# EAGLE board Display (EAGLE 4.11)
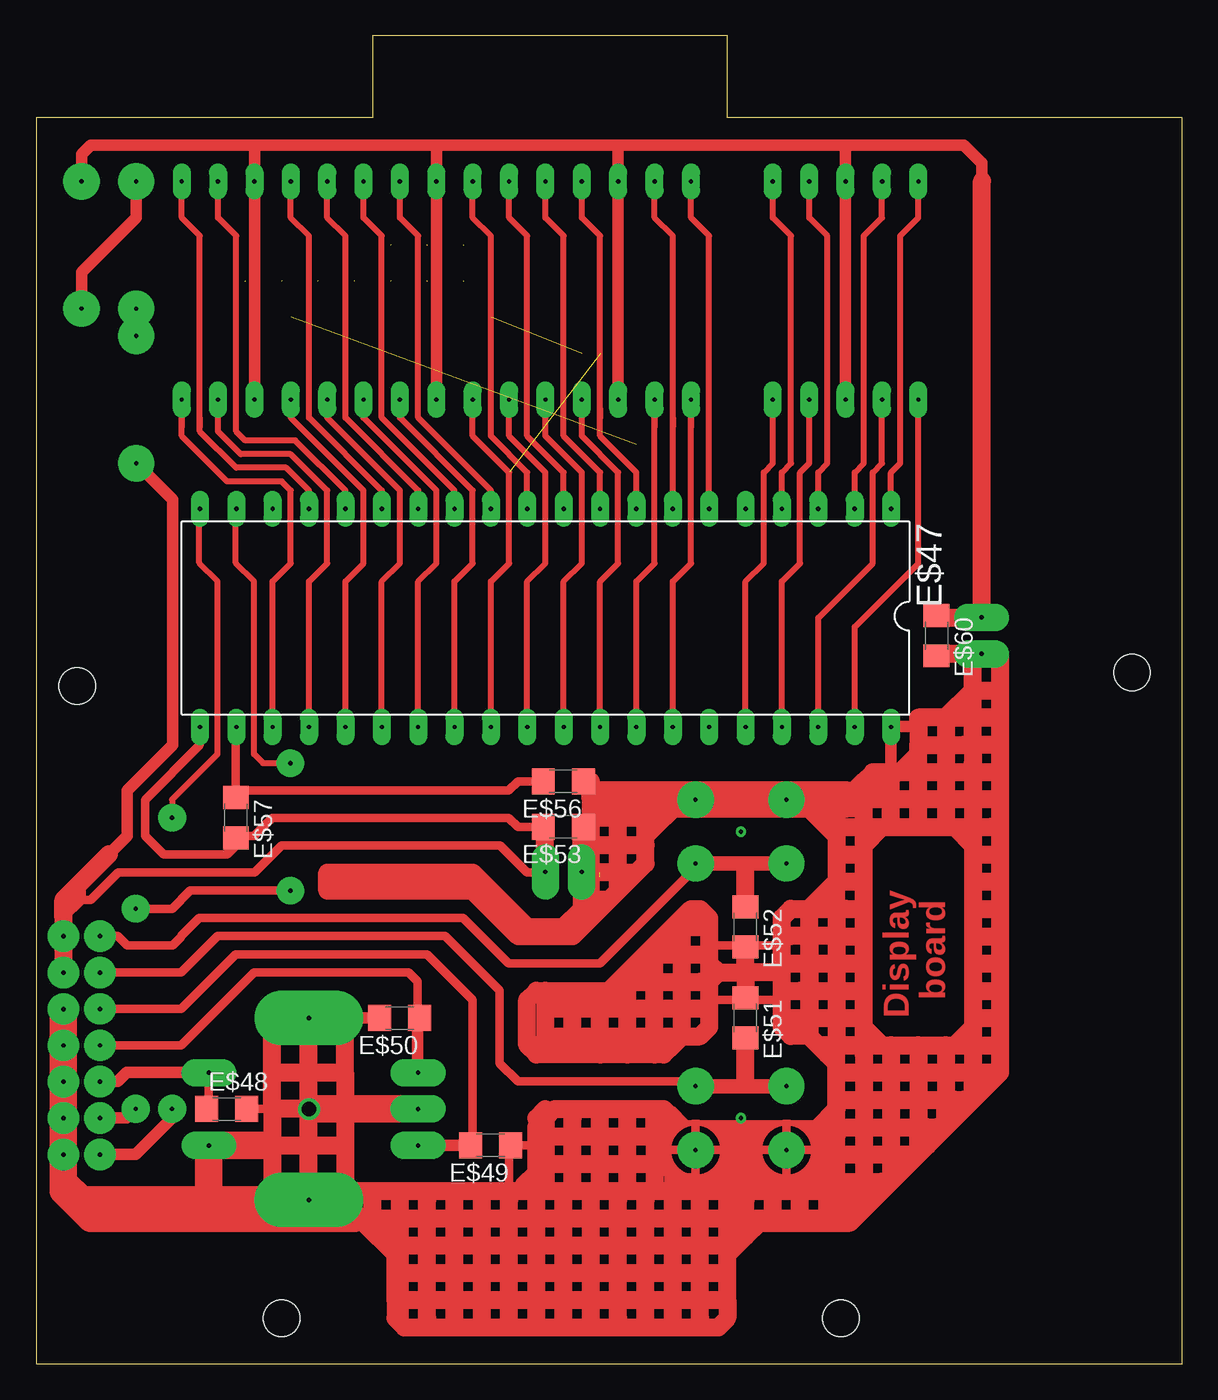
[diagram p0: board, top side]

Size 80.01 x 92.71 mm. Coordinates in mm from the lower left corner, seen from the top.
Outline: 80.01,0 80.01,87 48.26,87 48.26,92.71 23.5,92.71 23.5,87 0,87 0,0 80.01,0
Copper layers (1*16): Top 0.035mm / dielectric 1.5mm / Bottom 0.035mm
Design rules "default": minimum track width 10mil, minimum drill 24mil, track to track 8mil, track to pad 8mil, pad to pad 8mil, via to via 8mil, smd to smd 8mil, copper to edge 40mil, drill to drill 8mil, minimum pad ring 10mil, minimum via ring 8mil, stop-mask expansion 4mil, vias tented up to drill 0mil, thermal gap 10mil
Holes 2.54 mm at 2.86,47.31 76.52,48.26 17.14,3.17 56.2,3.17

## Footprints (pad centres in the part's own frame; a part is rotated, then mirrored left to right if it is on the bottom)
EC1,27 = drill 0.305 pad 1.27 long: P$1 0,0
EC1,9 = drill 0.305 pad 1.93 long: P$1 0,0
EC3,81 = drill 0.305 pad 3.81 long: P$1 0,0
DIL40 = drill 0.305 pad 1.27 long: 1 -24.13,-7.62; 2 -21.59,-7.62; 3 -19.05,-7.62; 4 -16.51,-7.62; 5 -13.97,-7.62; 6 -11.43,-7.62; 7 -8.89,-7.62; 8 -6.35,-7.62; 9 -3.81,-7.62; 10 -1.27,-7.62; 11 1.27,-7.62; 12 3.81,-7.62; 13 6.35,-7.62; 14 8.89,-7.62; 15 11.43,-7.62; 16 13.97,-7.62; 17 16.51,-7.62; 18 19.05,-7.62; 19 21.59,-7.62; 20 24.13,-7.62; 21 24.13,7.62; 22 21.59,7.62; 23 19.05,7.62; 24 16.51,7.62; 25 13.97,7.62; 26 11.43,7.62; 27 8.89,7.62; 28 6.35,7.62; 29 3.81,7.62; 30 1.27,7.62; 31 -1.27,7.62; 32 -3.81,7.62; 33 -6.35,7.62; 34 -8.89,7.62; 35 -11.43,7.62; 36 -13.97,7.62; 37 -16.51,7.62; 38 -19.05,7.62; 39 -21.59,7.62; 40 -24.13,7.62
C1206 = smd 1.6 x 1.8: 1 -1.4,0; 2 1.4,0

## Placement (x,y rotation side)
E$1  [EC1,27]  10.16,82.55 180 top
E$2  [EC1,27]  12.7,82.55 180 top
E$3  [EC1,27]  20.32,82.55 0 top
E$4  [EC1,27]  15.24,82.55 180 top
E$5  [EC1,27]  17.78,82.55 180 top
E$6  [EC1,27]  22.86,82.55 0 top
E$7  [EC1,27]  25.4,82.55 0 top
E$8  [EC1,27]  27.94,82.55 0 top
E$9  [EC1,27]  30.48,82.55 0 top
E$10  [EC1,27]  33.02,82.55 0 top
E$11  [EC1,27]  35.56,82.55 0 top
E$12  [EC1,27]  38.1,82.55 0 top
E$13  [EC1,27]  40.64,82.55 0 top
E$14  [EC1,27]  43.18,82.55 0 top
E$15  [EC1,27]  45.72,82.55 0 top
E$16  [EC1,27]  10.16,67.31 0 top
E$17  [EC1,27]  12.7,67.31 0 top
E$18  [EC1,27]  15.24,67.31 0 top
E$19  [EC1,27]  17.78,67.31 0 top
E$20  [EC1,27]  20.32,67.31 0 top
E$21  [EC1,27]  22.86,67.31 0 top
E$22  [EC1,27]  25.4,67.31 0 top
E$23  [EC1,27]  27.94,67.31 0 top
E$24  [EC1,27]  30.48,67.31 0 top
E$25  [EC1,27]  33.02,67.31 0 top
E$26  [EC1,27]  35.56,67.31 0 top
E$27  [EC1,27]  38.1,67.31 0 top
E$28  [EC1,27]  40.64,67.31 0 top
E$29  [EC1,27]  43.18,67.31 0 top
E$30  [EC1,27]  45.72,67.31 0 top
E$31  [EC1,27]  51.44,82.55 0 top
E$32  [EC1,27]  53.98,82.55 0 top
E$33  [EC1,27]  56.52,82.55 0 top
E$34  [EC1,27]  59.05,82.55 0 top
E$35  [EC1,27]  61.59,82.55 0 top
E$36  [EC1,27]  51.44,67.31 0 top
E$37  [EC1,27]  53.98,67.31 0 top
E$38  [EC1,27]  56.52,67.31 0 top
E$39  [EC1,27]  59.05,67.31 0 top
E$40  [EC1,27]  61.59,67.31 0 top
E$41  [EC1,9]  26.67,15.24 180 top
E$42  [EC1,9]  26.67,17.78 180 top
E$43  [EC1,9]  26.67,20.32 180 top
E$44  [EC1,9]  12.06,15.24 180 top
E$45  [EC1,9]  12.06,20.32 180 top
E$46  [EC3,81]  19.05,11.43 90 top
E$47  [DIL40]  35.56,52.07 180 top
E$48  [C1206]  13.3,17.79 0 top
E$49  [C1206]  31.73,15.25 180 top
E$50  [C1206]  25.37,24.14 180 top
E$51  [C1206]  49.52,24.14 270 top
E$52  [C1206]  49.52,30.49 270 top
E$53  [C1206]  36.81,37.48 180 top
E$54  [EC1,9]  35.55,34.33 270 top
E$55  [EC1,9]  38.09,34.33 270 top
E$56  [C1206]  36.81,40.66 180 top
E$57  [C1206]  13.94,38.12 270 top
E$58  [EC1,9]  66.01,49.56 0 top
E$59  [EC1,9]  66.01,52.1 0 top
E$60  [C1206]  62.86,50.82 270 top
E$61  [EC3,81]  19.05,24.14 90 top

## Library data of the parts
E$1-E$46 E$54 E$55 E$58 E$59 E$61 = Pads
E$47 = ic-package
E$48-E$53 E$56 E$57 E$60 = smd-ipc

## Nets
S$6: E$47.21
S$28: E$3.P$1 E$47.14
S$29: E$31.P$1 E$47.4
S$30: E$21.P$1 E$47.27
S$31: E$36.P$1 E$47.36
S$33: E$40.P$1 E$47.39
S$35: E$10.P$1 E$47.10
S$36: E$6.P$1 E$47.13
S$37: E$22.P$1 E$47.28
S$38: E$15.P$1 E$47.6
S$39: E$35.P$1 E$47.1
S$40: E$7.P$1 E$47.12
S$41: E$34.P$1 E$47.2
S$42: E$1.P$1 E$47.17
S$43: E$39.P$1 E$47.38
S$44: E$16.P$1 E$47.23
S$45: E$32.P$1 E$47.3
S$46: E$20.P$1 E$47.26
S$47: E$37.P$1 E$47.37
S$48: E$17.P$1
S$49: E$26.P$1 E$47.31
S$50: E$47.15
S$51: E$24.P$1 E$47.29
S$52: E$47.24
S$53: E$19.P$1 E$47.25
S$54: E$47.16
S$55: E$11.P$1 E$47.9
S$56: E$9.P$1 E$47.11
S$57: E$25.P$1 E$47.30
S$58: E$27.P$1 E$47.32
S$59: E$12.P$1 E$47.8
S$60: E$29.P$1 E$47.33
S$61: E$14.P$1 E$47.7
S$62: E$30.P$1 E$47.34
S$73: E$18.P$1 E$23.P$1 E$38.P$1

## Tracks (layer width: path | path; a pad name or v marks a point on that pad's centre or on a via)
S$1  (via drill 0.3 pad 2.18)
  other vias: 1.91,14.61
S$2  (via drill 0.3 pad 2.18)
  other vias: 1.91,17.14
S$3  (via drill 0.3 pad 2.18)
  other vias: 1.91,19.68
S$4  (via drill 0.3 pad 2.18)
  other vias: 1.91,22.23
S$5
  Top 0.61: 12.03,17.79 12.03,20.33
S$6
  Top 0.61: 7.62,37.47 7.62,36.83 8.89,35.56 13.34,35.56 13.97,36.2 | 7.62,37.47 7.62,38.1 | 7.62,37.47 7.62,39.37 11.43,43.18 E$47.21
S$7
  Top 1.27: 59.05,40.66 58.41,40.66
S$8  (via drill 0.3 pad 0.61)
  other vias: 49.21,17.14
S$9  (via drill 0.3 pad 2.54)
  other vias: 52.39,14.92
S$10
  Top 0.813: 29.82,15.25 26.64,15.25
S$11  (via drill 0.3 pad 2.18)  (1 unrouted)
  Top 0.61: 30.46,15.25 30.46,25.41 27.28,28.59 13.94,28.59 10.13,24.78 4.41,24.78
  other vias: 4.45,24.77
S$12  (via drill 0.3 pad 2.18)  (1 unrouted)
  Top 0.61: 46.34,19.69 33.63,19.69 32.36,20.96 32.36,26.05 28.55,29.86 12.67,29.86 10.13,27.32 4.41,27.32
  other vias: 4.45,27.3
S$13
  Top 0.406: 53.66,16.51 53.98,16.51
S$14
  Top 1.27: 38.08,34.31 38.08,37.48
S$15  (via drill 0.3 pad 0.61)
  other vias: 49.21,17.14
S$16
  Top 0.61: 13.3,35.58 14.57,36.85 15.21,36.85 16.48,38.12 33,38.12 33.63,37.48 35.54,37.48 | 35.54,34.31 34.27,34.31
  Top 1.27: 35.54,34.31 35.54,37.48
S$17  (via drill 1.02 pad 1.27)
  other vias: 19.05,17.78
S$18  (via drill 0.3 pad 2.54)  (1 unrouted)
  Top 1.016: v52.39,39.37 45.72,39.37
  other vias: 46.04,39.37
S$19  (via drill 0.3 pad 2.54)
  Top 1.016: v52.39,34.92 v46.04,34.92
S$20  (via drill 0.3 pad 2.54)
  Top 1.016: v52.39,19.37 45.72,19.37
S$21  (via drill 0.3 pad 2.54)
  other vias: 46.04,19.37
S$22  (via drill 0.3 pad 0.81)
  other vias: 17.14,3.17
S$23  (via drill 0.3 pad 0.81)
  other vias: 2.86,47.31
S$24  (via drill 0.3 pad 0.61)
  other vias: 49.21,37.15
S$25  (via drill 0.3 pad 0.81)
  other vias: 56.2,3.17
S$26  (via drill 0.3 pad 0.81)
  other vias: 76.52,48.26
S$27
  Top 0.61: 11.4,44.47 11.4,43.2
S$28
  Top 0.406: E$47.14 26.67,60.96 21.59,66.04 21.59,78.74 20.32,80.01 E$3.P$1
S$29
  Top 0.406: E$47.4 52.07,62.23 52.7,62.87 52.7,78.74 51.44,80.01 E$31.P$1
S$30
  Top 0.406: E$47.27 26.67,54.61 27.94,55.88 27.94,60.96 22.86,66.04 E$21.P$1
S$31
  Top 0.406: E$47.36 49.53,54.61 50.8,55.88 50.8,62.23 51.44,62.87 E$36.P$1
S$32
  Top 2.54: 17.11,10.8 12.03,10.8
S$33
  Top 0.406: E$47.39 57.15,51.44 61.59,55.88 E$40.P$1
S$34  (via drill 0.3 pad 2.18)  (1 unrouted)
  Top 0.813: 10.76,20.33 6.32,20.33 5.68,19.69 4.41,19.69
  other vias: 4.45,19.68
S$35
  Top 0.406: E$47.10 36.83,62.23 34.29,64.77 34.29,78.74 33.02,80.01 E$10.P$1
S$36
  Top 0.406: E$47.13 29.21,60.96 24.13,66.04 24.13,78.74 22.86,80.01 E$6.P$1
S$37
  Top 0.406: E$47.28 29.21,54.61 30.48,55.88 30.48,60.96 25.4,66.04 E$22.P$1
S$38
  Top 0.406: E$15.P$1 45.72,80.01 46.99,78.74 E$47.6
S$39
  Top 0.406: E$47.1 59.69,62.23 60.33,62.87 60.33,78.74 61.59,80.01 E$35.P$1
S$40
  Top 0.406: E$47.12 31.75,60.96 26.67,66.04 26.67,78.74 25.4,80.01 E$7.P$1
S$41
  Top 0.406: E$47.2 57.15,62.23 57.78,62.87 57.78,78.74 59.05,80.01 E$34.P$1
S$42
  Top 0.406: E$47.17 19.05,60.96 17.46,62.55 13.97,62.55 11.43,65.09 11.43,66.04 | E$1.P$1 10.16,80.01 11.43,78.74 11.43,66.04 | 11.43,66.04 11.43,65.41
S$43
  Top 0.406: E$47.38 54.61,52.07 58.42,55.88 58.42,62.23 59.05,62.87 E$39.P$1
S$44
  Top 0.406: E$47.23 16.51,54.61 17.78,55.88 17.78,60.96 17.14,61.59 13.34,61.59 10.16,64.77 10.16,66.04 | 10.16,66.04 10.16,65.41 | 10.16,66.04 E$16.P$1
S$45
  Top 0.406: E$47.3 54.61,62.23 55.24,62.87 55.24,78.74 53.98,80.01 E$32.P$1
S$46
  Top 0.406: E$47.26 24.13,54.61 25.4,55.88 25.4,60.96 20.32,66.04 E$20.P$1
S$47
  Top 0.406: E$47.37 52.07,54.61 53.34,55.88 53.34,62.23 53.98,62.87 E$37.P$1
S$48
  Top 0.406: 12.7,65.41 E$17.P$1
S$49
  Top 0.406: E$47.31 36.83,54.61 38.1,55.88 38.1,62.23 35.56,64.77 E$26.P$1 35.56,66.04
S$50
  Top 0.406: 17.78,83.19 17.78,80.01 19.05,78.74 19.05,66.04 24.13,60.96 E$47.15
S$51
  Top 0.406: E$47.29 31.75,54.61 33.02,55.88 33.02,62.23 30.48,64.77 E$24.P$1
S$52
  Top 0.406: 12.7,67.63 12.7,65.09 14.29,63.5 17.78,63.5 20.32,60.96 20.32,55.88 19.05,54.61 E$47.24
S$53
  Top 0.406: E$47.25 21.59,54.61 22.86,55.88 22.86,60.96 17.78,66.04 E$19.P$1
S$54
  Top 0.406: 12.7,83.19 12.7,80.01 13.97,78.74 13.97,65.09 14.61,64.45 18.1,64.45 21.59,60.96 E$47.16
S$55
  Top 0.406: E$47.9 39.37,62.23 36.83,64.77 36.83,78.74 35.56,80.01 E$11.P$1
S$56
  Top 0.406: E$9.P$1 30.48,80.01 31.75,78.74 31.75,64.77 34.29,62.23 E$47.11
S$57
  Top 0.406: E$47.30 34.29,54.61 35.56,55.88 35.56,62.23 33.02,64.77 E$25.P$1
S$58
  Top 0.406: E$47.32 39.37,54.61 40.64,55.88 40.64,62.23 38.1,64.77 E$27.P$1
S$59
  Top 0.406: E$47.8 41.91,62.23 39.37,64.77 39.37,66.67 | E$12.P$1 38.1,80.01 39.37,78.74 39.37,66.67 | 39.37,66.67 39.37,66.04
S$60
  Top 0.406: E$47.33 41.91,54.61 43.18,55.88 E$29.P$1 43.18,65.41
S$61
  Top 0.406: E$14.P$1 43.18,80.01 44.45,78.74 44.45,66.04 | 44.45,66.04 44.45,65.41 | E$47.7 44.45,66.04
S$62
  Top 0.406: E$47.34 44.45,54.61 45.72,55.88 E$30.P$1 45.72,65.41
S$63
  Top 1.27: 49.52,32.4 49.52,34.31
S$64
  Top 0.61: 16.48,17.79 14.57,17.79
  Top 1.27: 16.48,15.25 16.48,12.07 | 16.48,17.79 16.48,15.25 | 16.48,17.79 16.48,20.33 | 16.48,20.33 16.48,24.14 | 21.56,15.25 21.56,12.71 | 21.56,20.33 21.56,15.25 | 21.56,20.33 21.56,24.14 | 16.48,15.25 21.56,15.25 | 20.93,17.79 16.48,17.79 | 16.48,20.33 21.56,20.33
  Top 1.93: 26.64,17.79 20.93,17.79 19.66,17.79
S$65
  Top 1.27: 49.52,19.69 49.52,22.23
S$66
  Top 0.61: 43.5,14.92 48.58,14.92
S$67
  Top 0.61: 34.92,15.24 33.02,15.24 33.02,12.06
  Top 1.27: 43.81,17.78 43.81,16.51 | 43.81,17.78 36.2,17.78 35.56,17.14 | 35.56,17.14 35.56,15.88 | 35.56,15.88 35.56,13.97 | 35.56,13.97 35.56,12.06 | 35.56,17.14 34.92,16.51 34.92,15.24 34.92,13.34 33.97,12.38 | 43.81,17.78 44.45,17.14 | 43.18,15.88 43.18,14.29 | 43.18,14.29 43.18,13.97 35.56,13.97 | 43.18,15.88 43.18,17.14 | 35.56,15.88 43.18,15.88 | 43.18,14.29 43.18,12.7 | 23.18,10.16 51.44,10.16 | 51.44,10.16 53.34,10.16 | 53.34,10.16 55.24,10.16 | 55.24,10.16 56.2,10.16 56.2,11.43 | 24.77,8.26 48.26,8.26 | 48.26,8.26 48.58,8.26 | 33.02,2.54 25.72,2.54 25.08,3.17 25.08,4.45 | 33.02,2.54 36.83,2.54 | 36.83,2.54 38.73,2.54 | 38.73,2.54 42.55,2.54 | 42.55,2.54 47.62,2.54 48.26,3.17 48.26,4.45 | 25.08,4.45 25.08,6.35 | 25.08,6.35 25.08,7.62 22.86,9.84 | 48.26,4.45 48.26,7.62 49.53,8.89 | 49.53,8.89 50.48,9.84 56.83,9.84 62.23,15.24 | 25.08,4.45 48.26,4.45 | 25.08,6.35 47.94,6.35 | 33.02,2.54 33.02,11.43 | 21.91,12.06 23.5,12.06 | 23.5,12.06 25.4,12.06 | 25.4,12.06 31.11,12.06 | 31.11,12.06 33.02,12.06 34.92,12.06 | 34.92,12.06 36.83,12.06 | 36.83,12.06 37.47,12.06 | 37.47,12.06 44.45,12.06 | 44.45,12.06 46.35,12.06 | 46.35,12.06 48.26,12.06 | 48.26,12.06 51.44,12.06 | 51.44,12.06 53.34,12.06 | 53.34,12.06 57.15,12.06 | 37.47,12.06 37.47,17.14 | 25.4,3.17 25.4,12.06 | 31.11,3.17 31.11,12.06 | 34.92,3.17 34.92,12.06 | 36.83,2.54 36.83,12.06 | 38.73,2.54 38.73,11.43 | 42.55,2.54 42.55,11.43 | 44.45,3.17 44.45,12.06 | 46.35,3.17 46.35,12.06 | 48.26,8.26 48.26,12.06 | 49.53,8.89 49.53,11.43 | 51.44,10.16 51.44,12.06 | 53.34,10.16 53.34,12.06 | 55.24,10.16 55.24,11.43 | 23.5,9.53 23.5,12.06
S$69
  Top 1.27: 59.69,37.47 59.69,41.27
S$70
  Top 0.813: 26.64,20.33 26.64,23.51
S$71
  Top 0.813: 24.1,24.14 20.93,24.14
S$72
  Top 1.27: 19.02,12.07 19.02,23.51
S$73  (via drill 0.3 pad 2.54)
  Top 0.813: v3.17,82.55 3.17,84.45 3.81,85.09 15.88,85.09 | 40.64,67.94 40.64,85.09 27.94,85.09 | 27.94,85.09 E$23.P$1 | E$18.P$1 15.24,85.09 15.88,85.09 | 15.88,85.09 27.94,85.09 | 56.52,82.55 E$38.P$1 | 56.52,82.55 56.52,83.82 | 56.52,85.09 15.88,85.09 | 56.52,85.09 56.52,82.55 | 56.52,85.09 64.77,85.09 66.04,83.82 66.04,52.07
S$74  (via drill 0.3 pad 1.93, 0.3 pad 2.18)  (2 unrouted)
  Top 0.406: v17.75,41.93 15.85,41.93 15.21,42.56 15.21,54.64 13.94,55.91 13.94,59.72
  Top 0.813: v6.95,17.79 6.32,17.15 4.41,17.15
  other vias: 4.45,17.14
S$75  (via drill 0.3 pad 1.93, 0.3 pad 2.18)  (1 unrouted)
  Top 0.813: v9.49,17.79 9.49,17.15 6.95,14.61 4.41,14.61
  other vias: 4.45,14.61
S$76
  Top 1.93: 15.85,15.25 12.03,15.25
S$77
  Top 2.54: 12.06,10.79 3.81,10.79
S$78  (via drill 0.3 pad 2.18)  (1 unrouted)
  Top 0.61: 4.41,22.23 10.13,22.23 15.21,27.32 26.01,27.32 26.64,26.68 26.64,24.14
  other vias: 4.45,22.23
S$79  (via drill 0.3 pad 2.18, 0.3 pad 2.54)  (1 unrouted)
  Top 0.61: 3.17,32.38 1.91,31.11 | 3.17,32.38 1.91,32.38 | 3.17,32.38 3.17,33.66 | 3.17,32.38 3.81,32.38 5.71,34.29 15.24,34.29 17.14,36.2 32.38,36.2 34.29,34.29 34.92,34.29
  Top 0.813: 5.08,35.56 6.35,36.83 6.35,40.01 9.53,43.18 9.53,60.33 v6.99,62.87
  Top 1.27: 5.08,35.56 3.17,33.66 1.91,32.38 | 1.91,32.38 v1.91,27.3 | 1.91,31.11 1.91,32.38
S$80  (via drill 0.3 pad 2.18)  (1 unrouted)
  Top 0.61: 4.41,29.86 5.7,29.86 6.35,29.21 9.53,29.21 10.13,29.81 10.13,29.86 11.4,31.13 29.82,31.13 33,27.95 39.35,27.95 45.7,34.31
  Top 0.813: 45.7,34.94 45.7,34.31 46.34,34.94
  other vias: 4.45,29.84
S$81  (via drill 0.3 pad 2.18)  (1 unrouted)
  Top 1.93: v1.91,24.77 1.91,12.7 | 1.91,12.7 1.91,12.06 3.81,10.16 22.23,10.16 | 12.06,11.43 3.17,11.43 1.91,12.7
S$82
  Top 0.61: 35.54,40.66 33.63,40.66 33,40.02 13.94,40.02 13.94,44.47
S$83
  Top 0.406: 47.31,16.51 51.12,16.51
S$84
  Top 0.406: 47.62,16.19 50.8,16.19
S$85
  Top 0.406: 47.94,15.88 50.48,15.88
S$86
  Top 0.406: 47.94,15.56 50.48,15.56
S$87
  Top 0.406: 47.94,15.24 50.16,15.24
S$88
  Top 1.93: 12.03,14.61 12.03,11.44 16.48,11.44
S$89  (via drill 0.3 pad 2.18)  (1 unrouted)
  Top 1.27: v1.91,29.84 1.91,30.48
S$90
  Top 0.813: 61.59,44.47 59.68,44.47 59.68,41.29
  Top 1.27: 52.69,29.86 55.87,29.86 55.87,31.77 | 38.72,39.39 38.72,37.48 | 38.72,39.39 38.72,40.66 | 55.87,31.77 56.5,31.77 | 55.87,31.77 55.87,33.67 | 53.96,31.77 53.96,23.51 | 53.96,31.77 55.87,31.77 | 53.96,31.77 55.87,33.67 | 63.49,49.55 65.4,49.55 65.4,47.01 | 61.59,43.2 64.76,43.2 | 40.62,39.39 39.35,39.39 38.72,39.39 | 55.87,36.85 53.96,38.75 | 55.87,36.85 55.87,33.67 | 55.87,37.48 55.87,38.12 | 55.87,37.48 66.67,37.48 | 55.87,37.48 55.87,36.85 | 41.89,39.39 45.7,39.39 | 61.59,43.2 61.59,44.47 61.59,45.11 63.49,45.11 | 61.59,43.2 61.59,42.56 60.32,41.29 59.68,41.29 | 67.3,47.01 67.3,49.55 | 63.49,45.11 66.67,45.11 | 65.4,47.01 63.49,45.11 | 65.4,47.01 67.3,47.01 | 53.96,31.77 52.69,31.77 52.06,31.13 52.06,27.32 | 49.52,27.32 49.52,28.59 | 49.52,27.32 49.52,26.05 | 65.4,43.2 65.4,41.93 | 65.4,43.2 65.4,47.01 | 67.3,45.11 63.49,45.11 | 67.3,45.11 67.3,47.01 | 53.96,39.39 52.06,39.39 | 53.96,39.39 55.87,37.48 | 54.6,39.39 53.96,39.39 | 54.6,39.39 55.87,38.12 | 55.87,38.75 55.87,38.12 | 57.77,40.66 58.41,41.29 59.68,41.29 | 56.5,39.39 55.87,38.75 | 56.5,39.39 54.6,39.39 | 56.5,39.39 57.77,40.66 | 55.87,38.75 57.77,38.75 57.77,39.39 | 67.3,43.2 67.3,45.11 | 67.3,43.2 65.4,43.2 | 52.06,27.32 49.52,27.32 | 52.06,27.32 52.06,23.51 52.69,22.87 53.96,22.87 55.87,20.96 55.87,20.33 | 67.3,41.29 67.3,43.2 | 67.3,41.29 59.68,41.29 | 57.77,39.39 56.5,39.39 | 57.77,39.39 57.77,40.66 | 67.3,39.39 57.77,39.39 | 67.3,39.39 67.3,41.29 | 67.3,22.23 67.3,39.39 | 67.3,22.23 67.3,20.33 65.4,18.42 | 66.03,20.33 66.67,20.33 | 66.03,20.33 65.4,20.33 65.4,18.42 | 67.3,22.23 55.87,22.23 55.87,20.33 | 64.13,18.42 64.76,18.42 | 55.87,20.33 66.03,20.33 | 64.13,18.42 63.49,18.42 63.49,16.52
  Top 1.27: 63.49,16.52 65.4,18.42 | 59.68,13.34 59.68,14.61 60.32,14.61 | 62.22,16.52 62.86,16.52 | 62.22,16.52 61.59,16.52 61.59,14.61 | 55.87,18.42 55.87,20.33 | 55.87,18.42 64.13,18.42 | 55.87,16.52 55.87,18.42 | 55.87,16.52 62.22,16.52 | 60.32,14.61 60.95,14.61 | 61.59,14.61 63.49,16.52 | 61.59,14.61 58.41,11.44 57.77,11.44 | 55.87,14.61 60.32,14.61 | 55.87,14.61 55.87,16.52 | 55.87,13.34 54.6,12.07 | 55.87,13.34 55.87,14.61 | 55.87,12.71 59.05,12.71 | 55.87,12.71 55.87,13.34 | 55.87,12.07 55.23,12.71 | 55.87,12.07 55.87,12.71 | 55.87,12.07 56.5,11.44
  Top 1.93: 57.14,10.8 57.77,11.44 56.5,11.44
  Top 2.54: 41.89,39.39 41.26,39.39 | 41.89,39.39 39.35,39.39 | 41.89,39.39 53.96,39.39 56.5,39.39
S$91
  Top 0.813: 66.03,82.59 66.03,83.86
  Top 1.27: 66.03,52.09 66.03,82.59
S$92
  Top 1.27: 62.86,52.09 64.76,52.09
S$93
  Top 1.27: 38.1,32.38 38.1,31.75 | 38.1,31.75 38.1,30.48 | 38.1,30.48 37.47,29.84 33.66,29.84 30.48,33.02 20.32,33.02 20.32,34.29 30.48,34.29 34.29,30.48 36.83,30.48 | 37.47,30.48 36.83,30.48 | 36.83,30.48 38.1,31.75 | 38.1,31.75 38.1,33.66 | 38.1,30.48 40.01,32.38 | 40.01,32.38 40.64,33.02 | 40.64,33.02 41.91,34.29 | 41.91,34.29 42.55,34.92 42.55,36.2 | 42.55,36.2 42.55,36.83 | 42.55,36.83 45.09,39.37 | 40.01,32.38 38.73,32.38 | 40.64,34.29 38.1,34.29 | 40.64,33.02 40.64,34.29 | 40.64,34.29 40.64,39.37 | 42.55,36.83 42.55,38.73 | 42.55,36.2 38.73,36.2 | 38.73,36.2 38.73,38.1 43.18,38.1 | 40.64,34.29 41.91,34.29 | 38.73,33.02 38.73,36.2
S$94  (via drill 0.3 pad 1.93)  (2 unrouted)
  Top 0.406: 11.4,59.72 11.4,55.91 12.67,54.64 12.67,42.56 9.49,39.39 v9.49,38.12
  Top 0.61: v17.75,33.04 10.76,33.04 9.49,31.77 v6.95,31.77
S$95
  Top 1.27: 37.47,22.23 37.47,25.4
S$96  (via drill 0.3 pad 2.54)
  Top 0.813: v6.99,82.55 6.99,80.01 3.17,76.2 v3.17,73.66
S$97  (via drill 0.3 pad 2.54)
  other vias: 6.99,73.66
S$98  (via drill 0.3 pad 2.54)
  other vias: 6.99,71.75
S$99
  Top 0.61: 46.99,25.4 52.07,25.4 | 46.99,29.21 52.07,29.21
  Top 1.27: 47.62,27.3 49.53,27.3 | 46.99,26.67 47.62,27.3 | 45.09,22.86 46.35,22.86 46.99,23.5 46.99,24.77 | 44.45,22.23 43.81,21.59 43.18,21.59 | 44.45,22.23 45.09,22.86 | 43.18,21.59 41.27,21.59 | 41.27,21.59 39.37,21.59 | 39.37,21.59 34.92,21.59 34.29,22.23 34.29,25.4 34.92,26.04 35.56,26.04 | 35.56,26.04 40.01,26.04 | 40.01,26.04 42.55,28.57 | 42.55,28.57 43.18,29.21 | 43.18,29.21 44.45,30.48 | 44.45,30.48 45.09,31.11 | 45.09,31.11 45.72,31.75 46.35,31.75 46.99,31.11 46.99,30.48 | 46.99,30.48 46.99,29.21 46.99,28.57 | 46.99,28.57 46.99,27.94 | 46.99,27.94 46.99,26.67 | 46.99,26.67 46.99,25.4 46.99,24.77 | 45.09,22.86 45.09,31.11 | 43.18,21.59 43.18,29.21 | 41.27,21.59 41.27,26.67 46.35,26.67 | 39.37,21.59 39.37,25.4 | 35.56,22.23 35.56,22.86 | 35.56,22.86 35.56,24.77 | 35.56,24.77 35.56,26.04 | 46.99,24.77 35.56,24.77 | 40.64,25.4 40.01,26.04 | 34.92,22.23 44.45,22.23 | 35.56,22.86 45.09,22.86 | 42.55,28.57 46.99,28.57 | 44.45,30.48 46.99,30.48 | 47.62,27.3 46.99,27.94
S$100
  Top 1.27: 41.91,27.3 44.45,29.84
S$101
  Top 1.27: 61.59,37.47 61.59,42.55
S$102
  Top 1.27: 63.5,45.09 63.5,37.47
S$103  (via drill 0.3 pad 2.54)
  other vias: 46.04,14.92
S$104
  Top 0.406: 47.94,14.29 50.48,14.29
S$105
  Top 0.406: 47.94,13.97 48.26,13.97
S$106
  Top 1.27: 34.92,17.14 35.56,17.78
S$107
  Top 1.27: 65.41,42.55 65.41,36.2 | 65.41,36.2 65.41,35.56 | 65.41,35.56 65.41,33.66 | 65.41,33.66 65.41,31.75 | 65.41,22.23 65.41,21.59 | 65.41,21.59 65.41,19.05 | 65.41,31.75 65.41,29.84 | 65.41,29.84 65.41,27.94 | 65.41,27.94 65.41,26.04 | 65.41,26.04 65.41,24.13 | 65.41,24.13 65.41,23.5 | 65.41,23.5 65.41,21.59 | 65.41,24.13 67.31,24.13 | 65.41,26.04 67.31,26.04 | 65.41,27.94 67.31,27.94 | 65.41,29.84 67.31,29.84 | 65.41,31.75 67.31,31.75 | 65.41,33.66 67.31,33.66 | 65.41,35.56 67.31,35.56 | 64.14,37.47 65.41,36.2 | 64.14,22.23 65.41,23.5
S$109
  Top 1.27: 59.69,22.23 59.69,13.97
S$110
  Top 1.27: 61.59,22.23 61.59,15.24
S$111
  Top 1.27: 63.5,22.23 63.5,17.14
S$112
  Top 1.27: 54.61,15.88 55.88,15.88
S$113
  Top 1.27: 55.88,22.23 54.61,22.23
S$114
  Top 1.27: 54.61,22.23 53.98,22.86 53.98,29.84 | 54.61,22.23 55.24,21.59 | 57.15,22.23 55.88,22.23 | 55.88,22.23 54.61,22.23 | 55.88,22.23 55.88,29.84 57.78,29.84 | 52.07,24.13 52.7,24.13 | 52.7,24.13 53.98,24.13 | 52.07,26.04 53.34,26.04 | 53.34,26.04 53.98,26.04 | 52.07,27.94 53.34,27.94 | 53.34,27.94 53.98,27.94 | 57.78,22.23 57.78,21.59 | 57.78,21.59 57.78,12.7 | 57.78,21.59 57.78,23.5 | 57.78,23.5 57.78,24.13 | 57.78,24.13 57.78,26.04 | 57.78,26.04 57.78,27.94 | 57.78,27.94 57.78,29.84 | 57.78,29.84 57.78,31.75 | 57.78,31.75 57.78,33.66 | 57.78,33.66 57.78,35.56 | 57.78,35.56 57.78,36.2 | 57.78,36.2 57.78,39.37 | 53.34,27.94 57.78,27.94 | 53.34,26.04 57.78,26.04 | 52.7,24.13 57.78,24.13 | 55.24,31.75 57.78,31.75 | 55.88,33.66 57.78,33.66 | 55.88,35.56 57.78,35.56 | 57.78,36.2 59.05,37.47 | 57.78,23.5 59.05,22.23
S$115
  Top 0.406: 47.62,13.65 48.58,13.65
S$116
  Top 1.27: 41.27,12.06 41.27,17.14
S$117
  Top 1.27: 34.92,12.06 54.61,12.06
S$118
  Top 1.27: 55.88,17.78 54.61,16.51 55.88,16.51
S$119
  Top 1.27: 48.9,12.06 48.9,15.88
S$120
  Top 0.61: 46.04,13.97 46.04,12.7
S$121
  Top 0.61: 45.72,13.02 44.13,13.02 44.13,12.7 48.26,12.7
S$122
  Top 0.406: 47.31,13.34 48.58,13.34
S$123
  Top 0.61: 50.48,14.92 54.29,14.92
S$124
  Top 0.305: 45.4,16.83 54.61,16.83 55.24,16.83
  Top 0.406: 45.4,16.83 44.45,17.78 | 45.09,16.83 54.61,16.83
S$125
  Top 0.61: 44.77,16.51 43.81,15.56
S$126
  Top 0.406: 46.67,13.02 48.58,13.02
S$127
  Top 0.406: 49.21,12.7 51.75,12.7
S$128
  Top 0.406: 49.53,13.02 51.75,13.02
S$129
  Top 0.406: 50.16,13.65 50.8,13.65
S$130
  Top 0.406: 50.16,13.97 50.48,13.97
S$131
  Top 0.406: 53.98,13.34 54.61,13.34 | 53.66,13.02 53.98,13.34 | 53.98,13.34 54.29,13.02 54.61,13.02
S$132
  Top 0.406: 54.29,15.24 54.61,15.24
S$133
  Top 0.406: 53.98,13.65 54.61,13.65
S$134
  Top 0.406: 54.29,13.97 54.61,13.97
S$135
  Top 0.406: 54.29,14.29 54.61,14.29
S$136
  Top 0.406: 54.29,14.61 54.61,14.61
S$137
  Top 0.406: 43.5,13.34 44.45,13.34
S$138
  Top 0.813: 52.07,12.7 54.61,12.7
S$139
  Top 0.813: 54.93,13.02 54.93,15.24
S$140
  Top 0.406: 49.85,13.34 51.12,13.34
  Top 0.813: 49.85,13.34 49.85,14.92
S$141
  Top 0.406: 43.81,13.65 44.45,13.65
S$142
  Top 0.406: 47.94,14.61 50.16,14.61
  Top 0.813: 50.16,14.29 50.16,14.61
S$143
  Top 0.61: 52.39,16.51 52.39,13.02
S$144
  Top 0.61: 46.04,16.51 46.04,14.29
S$145
  Top 0.406: 43.81,13.97 44.13,13.97
S$146
  Top 0.406: 43.81,14.29 44.13,14.29
S$147
  Top 0.406: 43.81,14.61 44.13,14.61
S$148
  Top 0.406: 43.81,15.24 44.13,15.24
S$151
  Top 1.27: 39.37,12.38 39.37,17.46
S$152
  Top 1.27: 27.3,3.17 27.3,11.43
S$153
  Top 1.27: 29.21,3.17 29.21,11.43
S$154
  Top 1.27: 40.64,3.17 40.64,11.43
S$155
  Top 1.27: 24.13,9.53 24.77,8.89
(copper drawn outside any net)
  shapes: Top circle x2

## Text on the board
Top: board | Display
